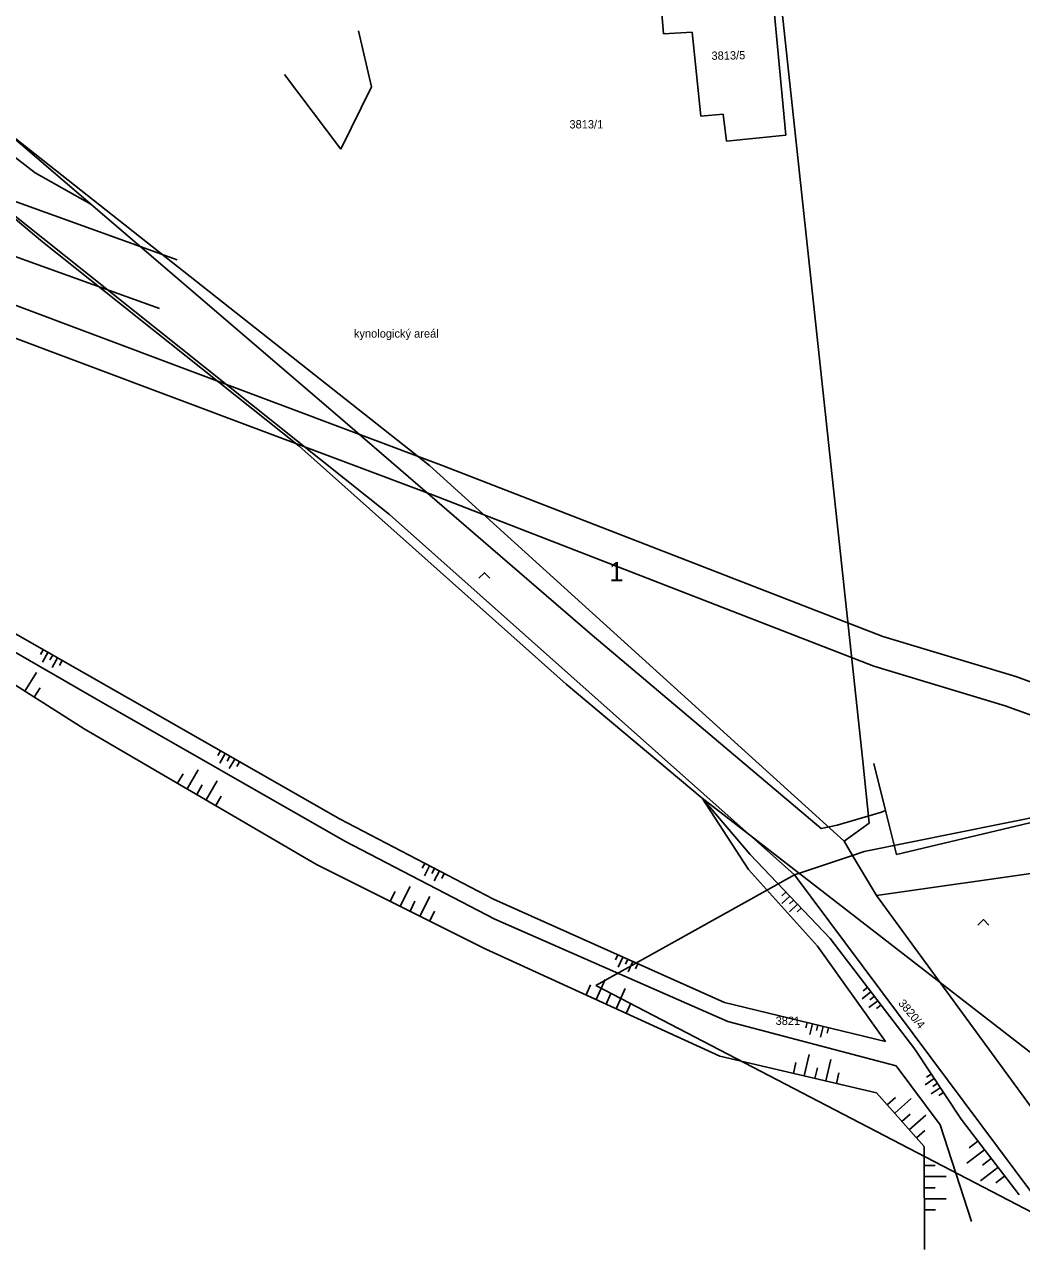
# Model space of a CAD drawing. Extents: x -540150 to -533593, y -1185082 to -1180066.
# Drawn here: x -536737.8 to -536647.3, y -1184260.2 to -1184149.1 of the extents above; entities that cross this region are included whole.
import ezdxf

# ---------------------------------------------------------------- set-up
doc = ezdxf.new("R2010")
doc.units = 0
for name, color, linetype in [('KN_HRAN_PARCEL', 7, 'Continuous'), ('KN_PARC_Č', 7, 'Continuous'), ('Vrstva 14', 7, 'Continuous'), ('Vrstva 15', 7, 'Continuous'), ('Vrstva 23', 7, 'Continuous'), ('Vrstva 36', 7, 'Continuous'), ('Vrstva 41', 7, 'Continuous'), ('Vrstva 7', 7, 'Continuous'), ('Vrstva 8', 7, 'Continuous')]:
    doc.layers.add(name, color=color, linetype=linetype)

msp = doc.modelspace()

# ---------------------------------------------------------------- linework, layer by layer
at = {"layer": 'KN_HRAN_PARCEL'}
for p, q in [((-536661.74, -1184215.95), (-536672.87, -1184112.49)), ((-536759.49, -1184143), (-536701.04, -1184189.14)), ((-536670.19, -1184143.55), (-536668.71, -1184159.18)), ((-536679.8, -1184149.99), (-536680.05, -1184147.04)), ((-536704.67, -1184193.59), (-536759.18, -1184150.12)), ((-536677.2, -1184149.84), (-536679.8, -1184149.99)), ((-536676.43, -1184157.45), (-536677.2, -1184149.84)), ((-536674.41, -1184157.27), (-536676.43, -1184157.45)), ((-536674.1, -1184159.72), (-536674.41, -1184157.27)), ((-536668.71, -1184159.18), (-536674.1, -1184159.72)), ((-536701.04, -1184189.14), (-536663.43, -1184223.2)), ((-536667.93, -1184226.27), (-536704.67, -1184193.59)), ((-536661.14, -1184221.57), (-536661.74, -1184215.95)), ((-536661.62, -1184224.15), (-536630.53, -1184217.86)), ((-536663.43, -1184223.2), (-536661.14, -1184221.57)), ((-536662.66, -1184224.5), (-536663.43, -1184223.2)), ((-536667.93, -1184226.27), (-536662.66, -1184224.5)), ((-536662.66, -1184224.5), (-536661.62, -1184224.15)), ((-536660.5, -1184228.14), (-536662.66, -1184224.5)), ((-536632.8, -1184224.2), (-536660.5, -1184228.14)), ((-536667.93, -1184226.27), (-536685.95, -1184236.3)), ((-536644.24, -1184258), (-536667.93, -1184226.27)), ((-536660.5, -1184228.14), (-536641.04, -1184254.77)), ((-536685.95, -1184236.3), (-536644.24, -1184258))]:
    msp.add_line(p, q, dxfattribs=at)
at = {"layer": 'Vrstva 14'}
for p, q in [((-536706.3, -1184154.79), (-536707.46, -1184149.71)), ((-536731.76, -1184165.44), (-536746.51, -1184152.8)), ((-536714.18, -1184153.69), (-536709.06, -1184160.44)), ((-536747.33, -1184154.48), (-536736.8, -1184162.61)), ((-536709.06, -1184160.44), (-536706.3, -1184154.79)), ((-536736.8, -1184162.61), (-536731.76, -1184165.44)), ((-536737.62, -1184170.55), (-536754.73, -1184164.37)), ((-536723.93, -1184170.5), (-536741.84, -1184164.03)), ((-536725.53, -1184174.91), (-536737.62, -1184170.55)), ((-536739.01, -1184174.46), (-536699.79, -1184189.16)), ((-536739.99, -1184177.09), (-536700.75, -1184191.8)), ((-536699.79, -1184189.16), (-536659.91, -1184204.63)), ((-536700.75, -1184191.8), (-536660.73, -1184207.32)), ((-536743.23, -1184201.78), (-536728.24, -1184210.3)), ((-536742.17, -1184204.03), (-536731.24, -1184210.34)), ((-536659.91, -1184204.63), (-536647.86, -1184208.27)), ((-536732.37, -1184213.01), (-536744.49, -1184205.33)), ((-536660.73, -1184207.32), (-536648.82, -1184210.92)), ((-536647.86, -1184208.27), (-536633.52, -1184213.53)), ((-536731.24, -1184210.34), (-536708.7, -1184223.21)), ((-536728.24, -1184210.3), (-536709.15, -1184221.22)), ((-536648.82, -1184210.92), (-536634.64, -1184216.12)), ((-536711.27, -1184225.32), (-536732.37, -1184213.01)), ((-536676.31, -1184219.32), (-536671.95, -1184224.4)), ((-536672.09, -1184225.78), (-536676.31, -1184219.32)), ((-536709.15, -1184221.22), (-536695.24, -1184228.47)), ((-536708.7, -1184223.21), (-536695.1, -1184230.28)), ((-536671.95, -1184224.4), (-536664.7, -1184232.03)), ((-536695.97, -1184232.97), (-536711.27, -1184225.32)), ((-536665.84, -1184232.72), (-536672.09, -1184225.78)), ((-536695.24, -1184228.47), (-536674.28, -1184237.84)), ((-536695.1, -1184230.28), (-536673.97, -1184239.56)), ((-536659.68, -1184241.38), (-536665.84, -1184232.72)), ((-536664.7, -1184232.03), (-536657.02, -1184242.07)), ((-536674.7, -1184242.71), (-536695.97, -1184232.97)), ((-536674.28, -1184237.84), (-536659.68, -1184241.38)), ((-536673.97, -1184239.56), (-536658.69, -1184243.57)), ((-536660.48, -1184246.03), (-536674.7, -1184242.71)), ((-536657.02, -1184242.07), (-536652.81, -1184248.43)), ((-536658.69, -1184243.57), (-536654.71, -1184248.92)), ((-536656.17, -1184250.89), (-536660.48, -1184246.03)), ((-536654.71, -1184248.92), (-536651.88, -1184257.71)), ((-536652.81, -1184248.43), (-536647.56, -1184255.29)), ((-536656.14, -1184260.24), (-536656.17, -1184250.89))]:
    msp.add_line(p, q, dxfattribs=at)
at = {"layer": 'Vrstva 15'}
for p, q in [((-536736.08, -1184205.84), (-536736.33, -1184206.28)), ((-536735.65, -1184206.09), (-536736.14, -1184206.96)), ((-536735.21, -1184206.33), (-536735.46, -1184206.77)), ((-536734.78, -1184206.58), (-536735.27, -1184207.45)), ((-536734.34, -1184206.83), (-536734.59, -1184207.26)), ((-536737.74, -1184209.6), (-536736.67, -1184207.91)), ((-536736.89, -1184210.14), (-536736.36, -1184209.29)), ((-536720, -1184215.01), (-536720.24, -1184215.45)), ((-536719.56, -1184215.26), (-536720.06, -1184216.13)), ((-536719.13, -1184215.51), (-536719.38, -1184215.94)), ((-536718.69, -1184215.76), (-536719.19, -1184216.63)), ((-536718.26, -1184216.01), (-536718.51, -1184216.44)), ((-536723.88, -1184217.96), (-536723.38, -1184217.1)), ((-536723.02, -1184218.46), (-536722.01, -1184216.74)), ((-536722.15, -1184218.97), (-536721.65, -1184218.1)), ((-536721.29, -1184219.47), (-536720.28, -1184217.74)), ((-536720.42, -1184219.98), (-536719.92, -1184219.11)), ((-536701.47, -1184225.22), (-536701.7, -1184225.66)), ((-536701.02, -1184225.45), (-536701.48, -1184226.34)), ((-536700.58, -1184225.68), (-536700.81, -1184226.13)), ((-536700.14, -1184225.91), (-536700.6, -1184226.8)), ((-536699.69, -1184226.15), (-536699.92, -1184226.59)), ((-536704.59, -1184228.66), (-536704.15, -1184227.76)), ((-536703.7, -1184229.1), (-536702.8, -1184227.31)), ((-536701.91, -1184230), (-536701.01, -1184228.21)), ((-536668.35, -1184228.19), (-536669.08, -1184228.87)), ((-536668.7, -1184227.82), (-536669.06, -1184228.17)), ((-536702.8, -1184229.55), (-536702.36, -1184228.66)), ((-536667.66, -1184228.91), (-536668.39, -1184229.6)), ((-536668.01, -1184228.55), (-536668.37, -1184228.89)), ((-536667.32, -1184229.27), (-536667.68, -1184229.62)), ((-536701.01, -1184230.44), (-536700.57, -1184229.55)), ((-536683.96, -1184233.51), (-536684.16, -1184233.97)), ((-536683.5, -1184233.71), (-536683.91, -1184234.63)), ((-536683.04, -1184233.92), (-536683.25, -1184234.37)), ((-536682.59, -1184234.12), (-536683, -1184235.04)), ((-536682.13, -1184234.33), (-536682.34, -1184234.78)), ((-536685.92, -1184237.57), (-536685.09, -1184235.75)), ((-536686.83, -1184237.15), (-536686.42, -1184236.24)), ((-536685.02, -1184237.98), (-536684.6, -1184237.07)), ((-536684.11, -1184238.4), (-536683.27, -1184236.58)), ((-536660.99, -1184236.88), (-536661.78, -1184237.49)), ((-536661.29, -1184236.48), (-536661.69, -1184236.79)), ((-536660.69, -1184237.28), (-536661.08, -1184237.58)), ((-536683.2, -1184238.82), (-536682.78, -1184237.91)), ((-536660.38, -1184237.67), (-536661.18, -1184238.28)), ((-536660.08, -1184238.07), (-536660.48, -1184238.37)), ((-536666.78, -1184239.65), (-536666.9, -1184240.14)), ((-536666.29, -1184239.77), (-536666.53, -1184240.74)), ((-536665.81, -1184239.89), (-536665.93, -1184240.38)), ((-536665.32, -1184240.01), (-536665.56, -1184240.98)), ((-536664.84, -1184240.13), (-536664.95, -1184240.61)), ((-536667.04, -1184244.49), (-536666.59, -1184242.55)), ((-536668.02, -1184244.27), (-536667.79, -1184243.29)), ((-536666.07, -1184244.72), (-536665.84, -1184243.75)), ((-536665.09, -1184244.95), (-536664.64, -1184243)), ((-536664.12, -1184245.18), (-536663.89, -1184244.2)), ((-536655.25, -1184244.74), (-536656.08, -1184245.3)), ((-536655.52, -1184244.33), (-536655.94, -1184244.6)), ((-536654.7, -1184245.58), (-536655.53, -1184246.13)), ((-536654.97, -1184245.16), (-536655.39, -1184245.44)), ((-536654.42, -1184246), (-536654.84, -1184246.27)), ((-536659.51, -1184247.13), (-536658.76, -1184246.46)), ((-536658.84, -1184247.87), (-536657.35, -1184246.55)), ((-536658.18, -1184248.62), (-536657.43, -1184247.96)), ((-536657.52, -1184249.37), (-536656.02, -1184248.04)), ((-536656.85, -1184250.12), (-536656.1, -1184249.45)), ((-536651.3, -1184250.4), (-536652.09, -1184251.01)), ((-536650.69, -1184251.2), (-536652.28, -1184252.41)), ((-536656.17, -1184252.63), (-536655.17, -1184252.63)), ((-536649.47, -1184252.79), (-536651.06, -1184254)), ((-536650.08, -1184251.99), (-536650.88, -1184252.6)), ((-536656.16, -1184253.63), (-536654.16, -1184253.63)), ((-536648.87, -1184253.58), (-536649.66, -1184254.19)), ((-536656.16, -1184254.63), (-536655.16, -1184254.63)), ((-536656.16, -1184255.63), (-536654.16, -1184255.63)), ((-536656.15, -1184256.63), (-536655.15, -1184256.63))]:
    msp.add_line(p, q, dxfattribs=at)
at = {"layer": 'Vrstva 23'}
for p, q in [((-536757.16, -1184151.2), (-536736.14, -1184168.86)), ((-536736.14, -1184168.86), (-536712.87, -1184187.35)), ((-536712.87, -1184187.35), (-536688.63, -1184208.97)), ((-536688.63, -1184208.97), (-536676.31, -1184219.32)), ((-536676.31, -1184219.32), (-536640.97, -1184246.69))]:
    msp.add_line(p, q, dxfattribs=at)
at = {"layer": 'Vrstva 36'}
for points in [[(-536696.55, -1184199.36), (-536696.05, -1184198.86), (-536695.55, -1184199.36)], [(-536651.29, -1184230.82), (-536650.79, -1184230.32), (-536650.29, -1184230.82)]]:
    msp.add_lwpolyline(points, dxfattribs=at)
at = {"layer": 'Vrstva 7'}
for p, q in [((-536709.55, -1184184.46), (-536731.76, -1184165.44)), ((-536686.27, -1184204.52), (-536709.55, -1184184.46)), ((-536665.52, -1184222.07), (-536686.27, -1184204.52)), ((-536660.04, -1184220.58), (-536659.67, -1184220.41)), ((-536640.68, -1184220.14), (-536658.68, -1184224.41)), ((-536664.07, -1184221.74), (-536665.52, -1184222.07))]:
    msp.add_line(p, q, dxfattribs=at)
msp.add_lwpolyline([(-536658.68, -1184224.41), (-536659.67, -1184220.41), (-536660.72, -1184216.16)], dxfattribs=at)
at = {"layer": 'Vrstva 8'}
msp.add_line((-536664.07, -1184221.74), (-536660.04, -1184220.58), dxfattribs=at)

# ---------------------------------------------------------------- texts
at = {"layer": 'KN_PARC_Č'}
for s, rotation, p in [('3813/5', 1, (-536675.45, -1184152.35)), ('3820/4', 310, (-536658.56, -1184237.93))]:
    msp.add_text(s, height=0.75, rotation=rotation, dxfattribs=at).set_placement(p)
for s, p in [('3813/1', (-536688.34, -1184158.57)), ('3821', (-536669.64, -1184239.87))]:
    msp.add_text(s, height=0.75, dxfattribs=at).set_placement(p)
at = {"layer": 'Vrstva 14'}
msp.add_text('1', height=1.75, dxfattribs=at).set_placement((-536684.73, -1184199.64))
at = {"layer": 'Vrstva 41'}
msp.add_text('kynologický areál', height=0.75, dxfattribs=at).set_placement((-536707.89, -1184177.54))

doc.saveas('drawing.dxf')
